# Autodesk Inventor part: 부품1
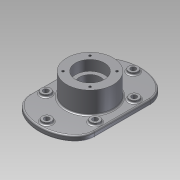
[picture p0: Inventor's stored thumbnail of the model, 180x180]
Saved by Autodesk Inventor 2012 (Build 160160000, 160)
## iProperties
Created: 2015-02
Part Number: 부품1
Material: Default
Document SubType Name: Modeling
Designer: Administrator
Density: 1 g/cm^3
Author: Administrator
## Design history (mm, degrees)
sketch "스케치2"
  geometry: L1 (-70, -60)-(70, -60); L2 (-70, 60)-(70, 60); L3 (0, 0)-(0, 60); L4 (70, 60)-(70, -60); L5 (-70, 60)-(-70, -60); L6 (0, 0)-(0, 110); L7 (0, 0)-(0, -110); C1 r 22.5 at (0, 0); 2 further points; 2 other entities
  constraints: 14 end point, 7 vertical, 2 coincident, 2 midpoint, 1 centre point, 1 perpendicular, 10 other
  dimensions: "d17" = 120 distance of point (0, -60) L3.end; "d18" = 60 distance of L3.end L3.start; "d19" = 140 distance between parallel lines of L4 L5; "d21" = 220 distance of L7.end L6.end; "d22" = 45 diameter of C1
extrude "돌출1" new body sketch "스케치2" distance "d24" = 12; taper "d25" = 0 deg
sketch "스케치3"
  geometry: C1 r 22.5 at (0, 0) reference; C2 r 50 at (0, 0)
  constraints: 1 centre point, 1 coincident
  dimensions: "d26" = 100 diameter of C2
extrude "돌출2" join sketch "스케치3" distance "d27" = 47; taper "d29" = 0 deg; dims "d28" = 23, "d30" = 0
sketch "스케치4"
  geometry: C1 r 22.5 at (0, 0) reference; C2 r 50 at (0, 0) reference; C3 r 31 at (0, 0)
  constraints: 1 centre point, 1 coincident
  dimensions: "d31" = 62 diameter of C3
extrude "돌출3" cut sketch "스케치4" distance "d32" = 22; taper "d33" = 0 deg
sketch "스케치5"
  geometry: C1 r 22.5 at (0, 0) reference; C2 r 50 at (0, 0) reference; C3 r 31 at (0, 0)
  constraints: 1 centre point, 1 coincident
  dimensions: "d34" = 62 diameter of C3
extrude "돌출4" cut sketch "스케치5" distance "d35" = 22; taper "d36" = 0 deg
sketch "스케치6"
  geometry: L1 (-70, -60)-(-70, 60) reference; L2 (70, 60)-(70, -60) reference; L3 (-53, -60)-(-53, 60); L4 (53, 60)-(53, -60); C1 r 50 at (0, 0) reference; C2 r 10 at (0, 93); C3 r 10 at (0, -93); C4 r 10 at (-53, 42); C5 r 10 at (53, 42); C6 r 10 at (-53, -42); C7 r 10 at (53, -42); 2 further points; 2 other entities
  constraints: 6 centre point, 4 end point, 4 point on line, 3 parallel, 10 other
  dimensions: "d37" = 20 diameter of C2; "d38" = 17 distance between parallel lines of L2 L4; "d39" = 93 distance of C2.centre C1.centre; "d40" = 20 diameter of C3; "d41" = 93 distance of C1.centre C3.centre; "d42" = 20 diameter of C4; "d43" = 20 diameter of C5; "d44" = 20 diameter of C6; "d45" = 20 diameter of C7; "d46" = 42 vertical distance of C4.centre C1.centre; "d47" = 42 vertical distance of C6.centre C1.centre; "d48" = 42 vertical distance of C5.centre C1.centre; "d49" = 42 vertical distance of C7.centre C1.centre
extrude "돌출5" join sketch "스케치6" distance "d50" = 5; taper "d51" = 0 deg
sketch "스케치8"
  geometry: C1 r 10 at (0, 0) reference; C2 r 5.5 at (0, 0); 1 further point
  constraints: 1 centre point, 1 coincident
  dimensions: "d54" = 11 diameter of C2
extrude "돌출6" cut sketch "스케치8" distance "d55" = 20; taper "d56" = 0 deg
sketch "스케치9"
  geometry: L1 (123, 18)-(123, -102) reference; L2 (-17, -102)-(-17, 18) reference; C1 r 10 at (0, 0) reference; C2 r 5.5 at (0, 0); C3 r 5.5 at (106, 0); C4 r 5.5 at (106, -84); C5 r 5.5 at (0, -84); 1 further point
  constraints: 4 centre point, 1 coincident
  dimensions: "d57" = 11 diameter of C2; "d58" = 11 diameter of C3; "d59" = 42 vertical distance of C3.centre point (53, -42); "d60" = 17 distance from line of C3.centre L1; "d61" = 11 diameter of C4; "d62" = 42 vertical distance of point (53, -42) C4.centre; "d63" = 17 distance from line of C4.centre L1; "d64" = 11 diameter of C5; "d65" = 17 distance from line of L2 C5.centre; "d66" = 42 vertical distance of C5.centre point (53, -42)
extrude "돌출7" cut sketch "스케치9" distance "d69" = 20; taper "d70" = 0 deg
sketch "스케치10"
  geometry: C1 r 10 at (0, 0) reference; C2 r 5.5 at (0, 0); 1 further point
  constraints: 1 centre point, 1 coincident
  dimensions: "d71" = 11 diameter of C2
extrude "돌출8" cut sketch "스케치10" distance "d72" = 20; taper "d73" = 0 deg
fillet "모깎기1" dims "d74" = 3
sketch "스케치11" dims "d75" = 82
  geometry: L1 (0, 41)-(0, -41); L2 (-41, 0)-(41, 0); L3 (0, 0)-(-28.991, 28.991); L4 (0, 0)-(28.991, -28.991); L5 (0, 0)-(28.991, 28.991); L6 (0, 0)-(-28.991, -28.991); C1 r 50 at (0, 0) reference; 4 further points
  constraints: 12 end point, 5 coincident, 2 collinear, 1 perpendicular, 1 vertical, 10 other
  dimensions: "d76" = 45 deg angle of L3 L1; "d77" = 45 deg angle of L1 L5
hole "구멍1" sketch "스케치11" at (-28.991, 28.991), (28.991, 28.991), (28.991, -28.991), (-28.991, -28.991) diameter "d78" = 4.917; stored, may be unused: countersink angle "d82" = 82 deg, drill point angle "d84" = 118 deg; dims "d79" = 10, "d80" = 3.023, "d81" = 2, "d83" = 8
node "솔리드1"
